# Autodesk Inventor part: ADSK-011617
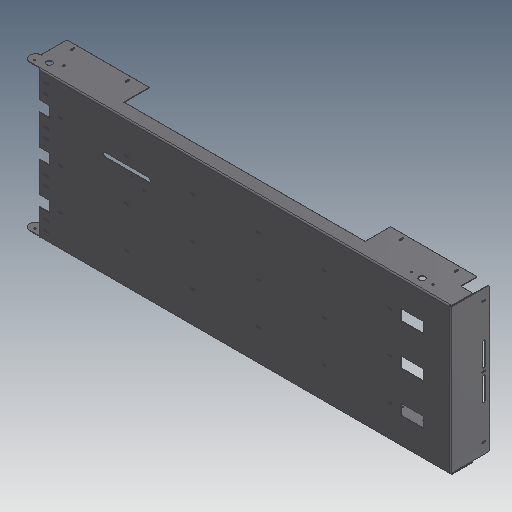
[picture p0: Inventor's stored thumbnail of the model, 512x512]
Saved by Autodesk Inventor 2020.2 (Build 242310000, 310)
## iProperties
Created: 2000-02
Part Number: ADSK-011617
Document SubType Name: Tôlerie
Designer: sspink
Material: 1.0312 DC05
Density: 1 g/cm^3
Sheet Metal Rule: Stahlblech 1.0312 - DC05 -   3.0 mm
Appearance: Metal-Steel(Polish)
Mass: 5749.93 g
Surface Area: 38684.9 cm^2
Volume: 5749.93 cm^3
Sheet Metal Width: 1028,072 mm
Sheet Metal Length: 2155,786 mm
Sheet Metal Area: 2216302,371 mm^2
Flat Pattern Width: 102.807 cm
Flat Pattern Length: 215.579 cm
Flat Pattern Area: 22163 cm^2
Control State: 0
Checked Out: False
Master: False
Shininess: 60.0
Length Units: 11269
Angle Units: 11279
Time Units: 11290
Mass Units: 11283
Length Display Precision: 3
Angle Display Precision: 2
Compacted: True
G_L: 1028,1x2155,8 mm
Thickness: 3,000 mm
Dimensions: 678,5x180x1981 mm
Mass: 5,75 kg
Semi finished: Stahlblech 1.0312 - DC05 -   3.0 mm
VLT_Material: 1.0312 DC05
Density: 0.0
Volumn: 0.0
Area: 0.0
PropertySet Name: Model Information
Author: sspink
Revision Number: -
Title: ADSK-011617
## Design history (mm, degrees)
node "Face1"
  sketch "Sketch1"
    geometry: L1 (-952.5, -339.25)-(952.5, -339.25); L2 (952.5, -339.25)-(952.5, 339.25); L3 (952.5, 339.25)-(-952.5, 339.25); L4 (-952.5, 339.25)-(-952.5, -339.25); 3 further points
    constraints: 8 end point, 2 midpoint, 2 parallel, 1 horizontal, 1 horizontal alignment, 1 perpendicular, 1 vertical alignment
    dimensions: "d0" = 1905 distance between parallel lines of L2 L4; "d1" = 678.5 distance between parallel lines of L1 L3
node "Lasche5"
node "Fläche4"
  sketch "Skizze30"
    geometry: L1 (1905, 174)-(0, 174) reference; L2 (1905, 0)-(0, 0) reference; L3 (0, 0)-(0, 174) reference; L4 (0, 174)-(-76, 174); L5 (-76, 174)-(-76, 0); L6 (-76, 0)-(0, 0); 1 further point
    constraints: 6 end point, 2 perpendicular, 1 horizontal
    dimensions: "d203" = 76 distance of L1.end L4.end
mirror "Spiegeln3"
node "Cut1" dims "d13" = 3 (= Thickness), "d14" = 0
  sketch "Sketch4"
    geometry: L1 (952.5, 176.8)-(952.5, 2.8) reference; L2 (952.5, 2.8)-(-952.5, 2.8) reference; C1 r 14.25 at (774.5, 135.8); C2 r 14.25 at (-952.5, 135.8); 1 further point
    constraints: 2 centre point, 1 horizontal alignment, 1 vertical alignment
    dimensions: "d200" = 28.5 diameter of C1; "d201" = 133 distance from line of C1.centre L2; "d202" = 178 distance from line of C1.centre L1; "d209" = 28.5 diameter of C2 (derived); "d294" = 1727 distance of C1.centre C2.centre (derived)
node "Cut3" dims "d30" = 3 (= Thickness), "d31" = 0
  sketch "Sketch8"
    geometry: L1 (723.5, 210.154)-(825.5, 210.154); L2 (825.5, 210.154)-(825.5, 160.154); L3 (825.5, 160.154)-(723.5, 160.154); L4 (723.5, 160.154)-(723.5, 210.154); L5 (723.5, 20.154)-(825.5, 20.154); L6 (825.5, 20.154)-(825.5, -29.846); L7 (825.5, -29.846)-(723.5, -29.846); L8 (723.5, -29.846)-(723.5, 20.154); L9 (723.5, -169.846)-(825.5, -169.846); L10 (825.5, -169.846)-(825.5, -219.846); L11 (825.5, -219.846)-(723.5, -219.846); L12 (723.5, -219.846)-(723.5, -169.846); L13 (952.5, 328.404)-(952.5, -338.096) reference; L14 (774.5, 210.154)-(774.5, -219.846); L15 (-952.5, -338.096)-(-952.5, 328.404) reference; L16 (-952.5, 210.154)-(-902.5, 210.154); L17 (-902.5, 210.154)-(-902.5, 160.154); L18 (-902.5, 160.154)-(-952.5, 160.154); L19 (-952.5, 160.154)-(-952.5, 210.154); L20 (-952.5, 20.154)-(-902.5, 20.154); L21 (-902.5, 20.154)-(-902.5, -29.846); L22 (-902.5, -29.846)-(-952.5, -29.846); L23 (-952.5, -29.846)-(-952.5, 20.154); L24 (-952.5, -169.846)-(-902.5, -169.846); L25 (-902.5, -169.846)-(-902.5, -219.846); L26 (-902.5, -219.846)-(-952.5, -219.846); L27 (-952.5, -219.846)-(-952.5, -169.846); 3 further points
    constraints: 50 end point, 12 parallel, 6 collinear, 6 horizontal, 6 perpendicular, 5 midpoint, 5 point on line, 4 equal length, 2 vertical alignment, 1 horizontal alignment
    dimensions: "d24" = 102 distance between parallel lines of L10 L12; "d26" = 50 distance between parallel lines of L5 L7; "d211" = 140 distance between parallel lines of L5 L3; "d212" = 140 distance between parallel lines of L9 L7 (derived); "d213" = 178 distance between parallel lines of L13 L14; "d231" = 50 distance of L16.start L16.end
node "Cut5" dims "d43" = 3 (= Thickness), "d44" = 0
  sketch "Sketch11"
    geometry: L1 (-952.5, 176.8)-(-952.5, 2.8) reference; L2 (-952.5, 2.8)-(-2933.5, 2.8) reference; L3 (-952.5, 2.8)-(-1009.5, 2.8); L4 (-1009.5, 2.8)-(-1009.5, 78.8); L5 (-1009.5, 78.8)-(-952.5, 78.8); L6 (-952.5, 78.8)-(-952.5, 2.8)
    constraints: 8 end point, 2 parallel, 1 horizontal, 1 perpendicular
    dimensions: "d214" = 57 distance of L4.end L5.end; "d215" = 76 distance of L3.end L4.end
node "Lasche7"
feature "Eckenrundung12" dims "d226" = 6
node "Cut6" dims "d51" = 3 (= Thickness), "d52" = 0
  sketch "Sketch13"
    geometry: L1 (-952.3, -173.952)-(-952.3, 0.048) reference; L2 (965.7, -173.952)-(-952.3, -173.952) reference; L3 (-952.3, -173.952)-(-927.3, -173.952); L4 (-927.3, -173.952)-(-927.3, -53.952); L5 (-927.3, -53.952)-(-952.3, -53.952); L6 (-952.3, -53.952)-(-952.3, -173.952)
    constraints: 8 end point, 2 parallel, 1 horizontal, 1 perpendicular
    dimensions: "d228" = 25 distance of L5.end L4.end; "d229" = 120 distance of L4.end L3.end
feature "Eckenrundung13" dims "d230" = 25
node "Cut9" dims "d73" = 3 (= Thickness), "d74" = 0
  sketch "Sketch16"
    geometry: L1 (889.5, 173.952)-(-1003.5, 173.952) reference; L2 (-622.5, 173.952)-(495, 173.952); L3 (495, 173.952)-(495, 56.452); L4 (495, 56.452)-(-622.5, 56.452); L5 (-622.5, 56.452)-(-622.5, 173.952); L6 (-1003.5, 53.952)-(-1003.5, 173.952) reference
    constraints: 8 end point, 2 parallel, 1 horizontal, 1 perpendicular, 1 point on line
    dimensions: "d232" = 1117.5 distance of L3.end L4.end; "d233" = 117.5 distance of L2.end L3.end; "d234" = 381 distance between parallel lines of L6 L5
node "Cut10" dims "d79" = 3 (= Thickness), "d80" = 0
  sketch "Sketch17"
    geometry: L1 (-957, -155.952)-(-950, -155.952); L2 (-950, -155.952)-(-950, -143.952); L3 (-950, -143.952)-(-957, -143.952); L4 (-957, -143.952)-(-957, -155.952); L5 (-622.5, -173.952)-(-1003.5, -173.952) reference; L6 (-1003.5, -53.952)-(-1003.5, -173.952) reference; A1 r 3.5 centre (-953.5, -143.952) between (-950, -143.952) and (-957, -143.952); A2 r 3.5 centre (-953.5, -155.952) between (-957, -155.952) and (-950, -155.952)
    constraints: 8 end point, 4 point on circle, 2 centre point, 2 parallel, 2 tangent, 1 horizontal, 1 perpendicular
    dimensions: "d75" = 12 distance of L3.end L1.start; "d76" = 7 distance of L2.end L3.end; "d235" = 50 distance from line of L6 A2.centre; "d236" = 18 distance from line of L5 A2.centre
node "Rectangular Pattern1" dims "d81" = 80, "d83" = 254
node "Cut11" dims "d88" = 3 (= Thickness), "d89" = 0
  sketch "Sketch18"
    geometry: L1 (154.952, -955.679)-(142.952, -955.679); L2 (142.952, -955.679)-(142.952, -948.679); L3 (142.952, -948.679)-(154.952, -948.679); L4 (154.952, -948.679)-(154.952, -955.679); L5 (167.952, -1002.179)-(-0.048, -1002.179) reference; L6 (173.952, -341.679)-(173.952, -996.179) reference; L7 (142.952, -952.179)-(154.952, -952.179); L8 (154.952, -389.179)-(142.952, -389.179); L9 (142.952, -389.179)-(142.952, -382.179); L10 (142.952, -382.179)-(154.952, -382.179); L11 (154.952, -382.179)-(154.952, -389.179); L12 (142.952, -385.679)-(154.952, -385.679); L13 (154.952, -672.429)-(142.952, -672.429); L14 (142.952, -672.429)-(142.952, -665.429); L15 (142.952, -665.429)-(154.952, -665.429); L16 (154.952, -665.429)-(154.952, -672.429); L17 (142.952, -668.929)-(154.952, -668.929); L18 (-0.048, -335.679)-(167.952, -335.679) reference; A1 r 3.5 centre (154.952, -952.179) between (154.952, -955.679) and (154.952, -948.679); A2 r 3.5 centre (142.952, -952.179) between (142.952, -948.679) and (142.952, -955.679); A3 r 3.5 centre (154.952, -385.679) between (154.952, -389.179) and (154.952, -382.179); A4 r 3.5 centre (142.952, -385.679) between (142.952, -382.179) and (142.952, -389.179); A5 r 3.5 centre (154.952, -668.929) between (154.952, -672.429) and (154.952, -665.429); A6 r 3.5 centre (142.952, -668.929) between (142.952, -665.429) and (142.952, -672.429); 2 further points
    constraints: 30 end point, 12 point on circle, 6 centre point, 6 parallel, 6 perpendicular, 6 tangent, 3 horizontal, 2 midpoint, 1 horizontal alignment
    dimensions: "d84" = 7 distance of L1.end L2.end; "d85" = 12 distance of L1.start L1.end; "d238" = 19 distance from line of L6 L7.end; "d239" = 7 distance of L8.end L9.end; "d240" = 12 distance of L8.start L8.end; "d241" = 7 distance of L13.end L14.end; "d242" = 12 distance of L13.start L13.end; "d243" = 50 distance between parallel lines of L5 L7; "d244" = 50 distance between parallel lines of L18 L12 (derived); "d245" = 19 distance between parallel lines of L6 L11 (derived); "d246" = 19 distance between parallel lines of L16 L6 (derived)
node "Cut12" dims "d97" = 3 (= Thickness), "d98" = 0
  sketch "Sketch19"
    geometry: L1 (2809.904, -549.179)-(2828.904, -549.179); L2 (2828.904, -549.179)-(2828.904, -556.179); L3 (2828.904, -556.179)-(2809.904, -556.179); L4 (2809.904, -556.179)-(2809.904, -549.179); L5 (2851.404, -455.179)-(2851.404, -336.929) reference; L6 (2902.404, -330.929)-(2851.404, -330.929) reference; L7 (2809.904, -594.179)-(2828.904, -594.179); L8 (2828.904, -594.179)-(2828.904, -601.179); L9 (2828.904, -601.179)-(2809.904, -601.179); L10 (2809.904, -601.179)-(2809.904, -594.179); L11 (2828.904, -377.054)-(2809.904, -377.054); L12 (2809.904, -370.054)-(2828.904, -370.054); L13 (2809.904, -377.054)-(2809.904, -370.054); L14 (2828.904, -370.054)-(2828.904, -377.054); L15 (2828.904, -415.054)-(2828.904, -422.054); L16 (2809.904, -415.054)-(2828.904, -415.054); L17 (2809.904, -422.054)-(2809.904, -415.054); L18 (2828.904, -422.054)-(2809.904, -422.054); L19 (2819.404, -556.179)-(2819.404, -594.179); L20 (952.404, -1003.429)-(952.404, -336.929) reference; L21 (952.404, -336.929)-(2851.404, -336.929) reference; L22 (2851.404, -455.179)-(2851.404, -336.929) reference; L23 (2851.404, -455.179)-(2801.404, -455.179) reference; L24 (2801.404, -455.179)-(2801.404, -505.179) reference; L25 (2801.404, -505.179)-(2851.404, -505.179) reference; L26 (2851.404, -645.179)-(2851.404, -505.179) reference; L27 (2851.404, -645.179)-(2801.404, -645.179) reference; L28 (2801.404, -645.179)-(2801.404, -695.179) reference; L29 (2801.404, -695.179)-(2851.404, -695.179) reference; L30 (2851.404, -835.179)-(2851.404, -695.179) reference; L31 (2851.404, -835.179)-(2801.404, -835.179) reference; L32 (2801.404, -835.179)-(2801.404, -885.179) reference; L33 (2801.404, -885.179)-(2851.404, -885.179) reference; L34 (2851.404, -1003.429)-(2851.404, -885.179) reference; L35 (2851.404, -1003.429)-(952.404, -1003.429) reference; L36 (1175.404, -695.179)-(1175.404, -645.179) reference; L37 (1175.404, -645.179)-(1073.404, -645.179) reference; L38 (1073.404, -645.179)-(1073.404, -695.179) reference; L39 (1073.404, -695.179)-(1175.404, -695.179) reference; L40 (1175.404, -505.179)-(1175.404, -455.179) reference; L41 (1175.404, -455.179)-(1073.404, -455.179) reference; L42 (1073.404, -455.179)-(1073.404, -505.179) reference; L43 (1073.404, -505.179)-(1175.404, -505.179) reference; L44 (1175.404, -885.179)-(1175.404, -835.179) reference; L45 (1175.404, -835.179)-(1073.404, -835.179) reference; L46 (1073.404, -835.179)-(1073.404, -885.179) reference; L47 (1073.404, -885.179)-(1175.404, -885.179) reference; L48 (2819.404, -377.054)-(2819.404, -415.054); A1 r 3.5 centre (2809.904, -552.679) between (2809.904, -549.179) and (2809.904, -556.179); A2 r 3.5 centre (2828.904, -552.679) between (2828.904, -556.179) and (2828.904, -549.179); A3 r 3.5 centre (2809.904, -597.679) between (2809.904, -594.179) and (2809.904, -601.179); A4 r 3.5 centre (2828.904, -597.679) between (2828.904, -601.179) and (2828.904, -594.179); A5 r 3.5 centre (2809.904, -373.554) between (2809.904, -370.054) and (2809.904, -377.054); A6 r 3.5 centre (2828.904, -373.554) between (2828.904, -377.054) and (2828.904, -370.054); A7 r 3.5 centre (2828.904, -418.554) between (2828.904, -422.054) and (2828.904, -415.054); A8 r 3.5 centre (2809.904, -418.554) between (2809.904, -415.054) and (2809.904, -422.054); 9 further points
    constraints: 36 end point, 16 point on circle, 12 midpoint, 8 centre point, 8 parallel, 8 tangent, 4 horizontal, 4 perpendicular, 3 vertical alignment, 2 horizontal alignment
    dimensions: "d93" = 7 distance of L3.end L1.start; "d94" = 19 distance of L1.start L1.end; "d247" = 22.5 distance between parallel lines of L5 L2; "d249" = 7 distance of L9.end L7.start; "d250" = 19 distance of L7.start L7.end; "d251" = 45 distance of A4.centre point (2828.904, -552.679); "d252" = 7 distance of L11.end L12.start; "d253" = 19 distance of L12.start L12.end; "d254" = 7 distance of L17.start L16.start; "d255" = 19 distance of L16.start L15.start; "d256" = 45 distance of A7.centre point (2828.904, -373.554)
node "Mirror1"
node "Cut13" dims "d112" = 3 (= Thickness), "d113" = 0
  sketch "Sketch20"
    geometry: L1 (1232.404, -670.179)-(1220.404, -670.179); L2 (1232.404, -673.679)-(1220.404, -673.679); L3 (1220.404, -666.679)-(1232.404, -666.679); L4 (1175.404, -695.179)-(1175.404, -645.179) reference; A1 r 3.5 centre (1232.404, -670.179) between (1232.404, -673.679) and (1232.404, -666.679); A2 r 3.5 centre (1220.404, -670.179) between (1220.404, -666.679) and (1220.404, -673.679); 2 further points
    constraints: 8 end point, 4 point on circle, 4 tangent, 2 centre point, 2 midpoint, 1 horizontal, 1 horizontal alignment, 1 parallel
    dimensions: "d257" = 7 distance between parallel lines of L2 L3; "d258" = 12 distance of L1.start L1.end; "d259" = 45 distance from line of L4 L1.end
node "Hole1" dims "d123" = 9, "d124" = 9.525, "d125" = 6.35, "d126" = 60 deg, "d127" = 19.05, "d128" = 118 deg, "d266" = 6
  sketch "Sketch21"
    geometry: L1 (724.5, 40.952)-(824.5, 40.952); C1 r 14.25 at (774.5, 40.952) reference; 1 further point
    constraints: 2 end point, 1 coincident, 1 horizontal, 1 horizontal alignment, 1 midpoint
    dimensions: "d293" = 100 distance of L1.start L1.end
node "Hole2" dims "d129" = 9, "d130" = 9.525, "d131" = 6.35, "d132" = 60 deg, "d133" = 19.05, "d134" = 118 deg, "d274" = 6
  sketch "Sketch22"
    geometry: L1 (2828.904, -556.179)-(2809.904, -556.179); L2 (2809.904, -549.179)-(2828.904, -549.179); L3 (2809.904, -556.179)-(2809.904, -549.179); L4 (2828.904, -549.179)-(2828.904, -556.179); L5 (2828.904, -594.179)-(2828.904, -601.179); L6 (2809.904, -594.179)-(2828.904, -594.179); L7 (2809.904, -601.179)-(2809.904, -594.179); L8 (2828.904, -601.179)-(2809.904, -601.179); L9 (-997.05, -18.252)-(-907.95, -63.652); L10 (-1003.5, 0.048)-(-952.5, 0.048) reference; C1 r 14.25 at (-952.5, -40.952) reference; A1 r 3.5 centre (2809.904, -552.679) between (2809.904, -549.179) and (2809.904, -556.179); A2 r 3.5 centre (2828.904, -552.679) between (2828.904, -556.179) and (2828.904, -549.179); A3 r 3.5 centre (2828.904, -597.679) between (2828.904, -601.179) and (2828.904, -594.179); A4 r 3.5 centre (2809.904, -597.679) between (2809.904, -594.179) and (2809.904, -601.179); 8 further points
    constraints: 18 end point, 8 point on circle, 5 midpoint, 4 centre point, 4 parallel, 4 tangent, 3 coincident, 2 horizontal, 2 perpendicular, 1 vertical alignment
    dimensions: "d267" = 7 distance of L1.end L2.start; "d268" = 19 distance of L2.start L2.end; "d269" = 7 distance of L7.start L6.start; "d270" = 19 distance of L6.start L5.start; "d271" = 45 distance of A3.centre point (2828.904, -552.679); "d272" = 100 distance of L9.start L9.end; "d273" = 27 deg angle of L10 L9
node "Cut14" dims "d139" = 3 (derived), "d140" = 0
  sketch "Sketch23"
    geometry: L1 (-647.5, 139.904)-(-447.5, 139.904); L2 (-647.5, 129.904)-(-447.5, 129.904); L3 (-447.5, 149.904)-(-647.5, 149.904); L4 (-1424.7, -6.096)-(1348.7, -6.096) reference; L5 (-952.5, 18.904)-(-952.5, 158.904) reference; A1 r 10 centre (-647.5, 139.904) between (-647.5, 149.904) and (-647.5, 129.904); A2 r 10 centre (-447.5, 139.904) between (-447.5, 129.904) and (-447.5, 149.904); 1 further point
    constraints: 8 end point, 4 point on circle, 4 tangent, 2 centre point, 1 horizontal, 1 midpoint, 1 parallel
    dimensions: "d275" = 20 diameter of A2; "d276" = 200 distance of L1.start L1.end; "d277" = 146 distance between parallel lines of L4 L1; "d278" = 305 distance from line of L5 L1.start
node "Hole3" dims "d146" = 9, "d147" = 9.525, "d148" = 6.35, "d149" = 60 deg, "d150" = 19.05, "d151" = 118 deg, "d283" = 6
  sketch "Sketch24"
    geometry: L1 (-525.197, 116.321)-(-465.5, 85.904); L2 (-447.5, 129.904)-(-647.5, 129.904) reference; A1 r 10 centre (-447.5, 139.904) between (-447.5, 129.904) and (-447.5, 149.904) reference; 2 further points
    constraints: 2 coincident, 2 end point
    dimensions: "d279" = 27 deg angle of L2 L1; "d280" = 67 distance of L1.start L1.end; "d281" = 54 vertical distance of A1.centre L1.end; "d282" = 18 horizontal distance of A1.centre L1.end
node "Cut15" dims "d156" = 3 (derived), "d157" = 0
  sketch "Sketch25"
    geometry: L1 (148.952, -648.929)-(148.952, -548.929); L2 (154.952, -648.929)-(154.952, -548.929); L3 (142.952, -548.929)-(142.952, -648.929); L4 (173.952, -341.679)-(173.952, -996.179) reference; L5 (142.952, -665.429)-(154.952, -665.429) reference; A1 r 6 centre (148.952, -648.929) between (142.952, -648.929) and (154.952, -648.929); A2 r 6 centre (148.952, -548.929) between (154.952, -548.929) and (142.952, -548.929); A3 r 3.5 centre (142.952, -668.929) between (142.952, -665.429) and (142.952, -672.429) reference; 1 further point
    constraints: 8 end point, 4 point on circle, 4 tangent, 2 centre point, 1 midpoint, 1 parallel, 1 vertical
    dimensions: "d284" = 100 distance of L1.start L1.end; "d285" = 12 diameter of A2; "d286" = 25 distance between parallel lines of L4 L1; "d287" = 20 vertical distance of A3.centre L1.start
node "Mirror2"
node "Cut16" dims "d162" = 3 (derived), "d163" = 0
  sketch "Sketch27"
    geometry: L1 (675.5, -148.952)-(775.5, -148.952); L2 (675.5, -153.952)-(775.5, -153.952); L3 (775.5, -143.952)-(675.5, -143.952); L4 (889.5, -173.952)-(495, -173.952) reference; L5 (895.5, -167.952)-(895.5, -103.952) reference; A1 r 5 centre (675.5, -148.952) between (675.5, -143.952) and (675.5, -153.952); A2 r 5 centre (775.5, -148.952) between (775.5, -153.952) and (775.5, -143.952); 1 further point
    constraints: 8 end point, 4 point on circle, 4 tangent, 2 centre point, 1 horizontal, 1 midpoint, 1 parallel
    dimensions: "d289" = 100 distance of L1.start L1.end; "d290" = 10 diameter of A2; "d291" = 25 distance between parallel lines of L4 L1; "d292" = 120 distance from line of L5 L1.end
workplane "Arbeitsebene3"
workplane "Arbeitsebene4"
node "Solide1"
node "Corps solides"
node "Corps surfaciques"
pattern_linear "Rechteckige Anordnung6" dims "d262" = 305, "d265" = 190
node "Plate1" dims "d179" = 3 (derived)
sketch "Skizze28"
  geometry: L1 through (952.5, 0) direction (-1, 0); L2 through (0, -90) direction (0, -1); L3 (0, -180)-(1905, -180); L4 (1905, -180)-(1905, 0)
  constraints: 6 end point, 1 horizontal, 1 perpendicular, 1 vertical
feature "Grobblech8" dims "d179" = 3 (derived), "d180" = 3 (derived), "d181" = 1.5 (derived), "d182" = 6 (derived), "d183" = 3 (derived), "d184" = 180, "d185" = 90 deg, "d186" = 3 (derived), "d187" = 12 (derived), "d188" = 3 (derived), "d189" = 3 (derived), "SeamGap" = 0.00508
feature "Biegung7" dims "d179" = 3 (derived), "d180" = 3 (derived), "d181" = 1.5 (derived), "d182" = 6 (derived), "d183" = 3 (derived), "d184" = 180, "d185" = 90 deg, "d186" = 3 (derived), "SeamGap" = 0.00508
feature "Ecke1" dims "d184" = 180, "d185" = 90 deg, "d187" = 12 (derived), "d188" = 3 (derived), "d189" = 3 (derived)
feature "Grobblech10" dims "d179" = 3 (derived), "d204" = 3 (derived), "d205" = 3 (derived), "d207" = 6 (derived)
feature "Biegung9" dims "d179" = 3 (derived), "d204" = 3 (derived), "d205" = 3 (derived), "d206" = 1.5 (derived), "d207" = 6 (derived), "d208" = 3 (derived), "SeamGap" = 0.00508
sketch "Skizze31"
  geometry: L1 through (333.25, 0) direction (-1, 0); L2 through (0, -90) direction (0, -1); L3 (0, -180)-(666.5, -180); L4 (666.5, -180)-(666.5, 0)
  constraints: 6 end point, 1 horizontal, 1 perpendicular, 1 vertical
feature "Grobblech11" dims "d179" = 3 (derived), "d216" = 3 (derived), "d217" = 1.5 (derived), "d218" = 6 (derived), "d219" = 3 (derived), "d220" = 180, "d221" = 90 deg, "d222" = 3 (derived), "d223" = 12 (derived), "d224" = 3 (derived), "d225" = 3 (derived), "SeamGap" = 0.00508
feature "Biegung10" dims "d179" = 3 (derived), "d216" = 3 (derived), "d217" = 1.5 (derived), "d218" = 6 (derived), "d219" = 3 (derived), "d220" = 180, "d221" = 90 deg, "d222" = 3 (derived), "SeamGap" = 0.00508
feature "Ecke3" dims "d220" = 180, "d221" = 90 deg, "d223" = 12 (derived), "d224" = 3 (derived), "d225" = 3 (derived)
node "Projizierte Kontur1"
feature "Definition1"
other parameters: "Thickness" = 3 (derived), "BendRadius" = 3 (derived), "BendReliefWidth" = 3 (derived), "BendReliefDepth" = 1.5 (derived), "CornerReliefSize" = 12 (derived), "MinimumRemnant" = 6 (derived), "d2" = 3 (= BendRadius), "d3" = 177.8, "d4" = 90 deg, "d5" = 3 (= BendRadius), "d45" = 177.8, "d46" = 90 deg, "d47" = 3 (= BendRadius), "TransitionRadius" = 3 (derived), "TailleRayonJacobi" = 3 (derived), "TailleJeu" = 3 (derived), "BendRadius" = 3, "BendReliefDepth" = 1.5, "BendReliefWidth" = 3, "CornerReliefSize" = 12, "MinimumRemnant" = 6, "TailleJeu" = 3, "TailleRayonJacobi" = 3, "Thickness" = 3, "TransitionRadius" = 3
